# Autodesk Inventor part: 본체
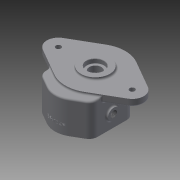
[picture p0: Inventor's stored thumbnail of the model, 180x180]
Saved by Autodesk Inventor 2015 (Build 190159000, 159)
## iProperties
Created: 2025-11
Part Number: 본체
Material: 일반
Document SubType Name: Modeling
Designer: user
Density: 1 g/cm^3
Appearance: 기본값
Author: user
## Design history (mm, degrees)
sketch "스케치1"
  geometry: L1 (-74, 17.321)-(-26, 45.033); L2 (-74, -17.321)-(-26, -45.033); L3 (26, 45.033)-(74, 17.321); L4 (74, -17.321)-(26, -45.033); A1 r 52 centre (0, 0) between (-26, 45.033) and (-26, -45.033); A2 r 20 centre (-64, 0) between (-74, 17.321) and (-74, -17.321); A3 r 20 centre (64, 0) between (74, -17.321) and (74, 17.321); 1 further point
  constraints: 8 end point, 8 point on circle, 8 tangent, 3 centre point, 2 horizontal alignment, 1 coincident
  dimensions: "d0" = 104 diameter of A1; "d1" = 40 diameter of A2; "d2" = 40 diameter of A3; "d3" = 128 distance of A3.centre A2.centre; "d4" = 64 distance of A3.centre point (0, 0)
extrude "돌출1" new body sketch "스케치1" distance "d5" = 12; taper "d6" = 0 deg
sketch "스케치2"
  geometry: C1 r 10 at (64, 0); C2 r 10 at (-64, 0); A1 r 20 centre (64, 0) between (74, -17.321) and (74, 17.321) reference; A2 r 20 centre (-64, 0) between (-74, 17.321) and (-74, -17.321) reference
  constraints: 2 centre point, 2 coincident
  dimensions: "d7" = 20 diameter of C1; "d8" = 20 diameter of C2
extrude "돌출2" join sketch "스케치2" distance "d9" = 3; taper "d10" = 0 deg
sketch "스케치3"
  geometry: A1 r 20 centre (-64, 0) between (-74, 17.321) and (-74, -17.321) reference; A2 r 20 centre (64, 0) between (74, -17.321) and (74, 17.321) reference
hole "구멍1" sketch "스케치3" at (-64, 0), (64, 0) diameter "d11" = 9; stored, may be unused: countersink angle "d15" = 90 deg, drill point angle "d17" = 118 deg; dims "d12" = 6.35, "d13" = 4, "d14" = 2, "d16" = 9.525
sketch "스케치4"
  geometry: L1 (19, -64.909)-(37.5, -54.228); L2 (45, -41.238)-(45, 9.238); L3 (37.5, 22.228)-(19, 32.909); L4 (0, -75.879)-(0, 43.879); L5 (-45, -41.238)-(-45, 9.238); L6 (-19, -64.909)-(-37.5, -54.228); L7 (-37.5, 22.228)-(-19, 32.909); L8 (-45, -16)-(45, -16); A1 r 52 centre (0, 0) between (26, 45.033) and (-26, 45.033) reference; A2 r 52 centre (0, 0) between (-26, -45.033) and (26, -45.033) reference; A3 r 38 centre (0, -32) between (-19, -64.909) and (19, -64.909); A4 r 38 centre (0, 0) between (19, 32.909) and (-19, 32.909); A5 r 15 centre (-30, -41.238) between (-45, -41.238) and (-37.5, -54.228); A6 r 15 centre (30, -41.238) between (37.5, -54.228) and (45, -41.238); A7 r 15 centre (30, 9.238) between (45, 9.238) and (37.5, 22.228); A8 r 15 centre (-30, 9.238) between (-37.5, 22.228) and (-45, 9.238); 6 further points
  constraints: 16 end point, 14 point on circle, 13 point on line, 12 tangent, 6 centre point, 4 equal radius, 2 horizontal alignment, 2 midpoint, 2 symmetric about line, 2 vertical, 2 vertical alignment, 1 coincident
  dimensions: "d19" = 90 distance between parallel lines of L5 L2; "d20" = 60 deg angle of L3 L1; "d23" = 16 distance from line of L8 A1.centre; "d25" = 38 radius of A3; "d26" = 15 radius of A5; "d33" = 32 distance of A3.centre A1.centre
node "작업 평면1"
extrude "돌출4" join sketch "스케치4" distance "d34" = 48; taper "d36" = 0 deg; dims "d35" = 8, "d37" = 0
sketch "스케치5"
  geometry: C1 r 25 at (0, 0); A1 r 52 centre (0, 0) between (26, 45.033) and (-26, 45.033) reference
  constraints: 1 centre point, 1 coincident
  dimensions: "d38" = 50 diameter of C1
extrude "돌출5" join sketch "스케치5" distance "d39" = 4; taper "d40" = 0 deg
sketch "스케치8"
  geometry: L1 (45, -41.238)-(45, 9.238) reference; L2 (16, -23.754)-(16, -8.246); L3 (-16, -23.754)-(-16, -8.246); A1 r 38 centre (0, -32) between (-19, -64.909) and (19, -64.909) reference; A2 r 38 centre (0, 0) between (19, 32.909) and (-19, 32.909) reference; A3 r 18 centre (0, -32) between (16, -23.754) and (-16, -23.754); A4 r 18 centre (0, 0) between (16, -8.246) and (-16, -8.246)
  constraints: 4 end point, 4 point on circle, 2 centre point, 2 coincident, 2 parallel
  dimensions: "d41" = 36 diameter of A3; "d42" = 36 diameter of A4; "d43" = 32 distance between parallel lines of L2 L3; "d44" = 16 distance from line of A3.centre L2
extrude "돌출6" cut sketch "스케치8" distance "d45" = 31; taper "d46" = 0 deg
sketch "스케치9"
  geometry: C1 r 25 at (0, 0) reference
hole "구멍2" sketch "스케치9" at (0, 0) diameter "d47" = 21; stored, may be unused: countersink angle "d51" = 90 deg, drill point angle "d53" = 118 deg; dims "d48" = 6.35, "d49" = 30, "d50" = 7.3, "d52" = 9.525
sketch "스케치10"
  geometry: L1 (-16, -8.246)-(-16, -23.754) reference; L2 (16, -23.754)-(16, -8.246) reference; L3 (-37.5, 22.228)-(-19, 32.909) reference; L4 (19, 32.909)-(37.5, 22.228) reference; L5 (45, 9.238)-(45, -41.238) reference; L6 (37.5, -54.228)-(19, -64.909) reference; L7 (-19, -64.909)-(-37.5, -54.228) reference; L8 (-45, -41.238)-(-45, 9.238) reference; C1 r 10.5 at (0, 0) reference; C2 r 10.5 at (0, 0) reference; C3 r 11.5 at (0, 0); A1 r 18 centre (0, -32) between (-16, -23.754) and (16, -23.754) reference; A2 r 18 centre (0, 0) between (16, -8.246) and (-16, -8.246) reference; A3 r 38 centre (0, 0) between (19, 32.909) and (-19, 32.909) reference; A4 r 15 centre (30, 9.238) between (45, 9.238) and (37.5, 22.228) reference; A5 r 15 centre (30, -41.238) between (37.5, -54.228) and (45, -41.238) reference; A6 r 38 centre (0, -32) between (-19, -64.909) and (19, -64.909) reference; A7 r 15 centre (-30, -41.238) between (-45, -41.238) and (-37.5, -54.228) reference; A8 r 15 centre (-30, 9.238) between (-37.5, 22.228) and (-45, 9.238) reference
  constraints: 1 centre point, 1 coincident
  dimensions: "d54" = 23 diameter of C3
extrude "돌출7" cut sketch "스케치10" distance "d55" = 15; taper "d56" = 0 deg
sketch "스케치11"
  geometry: C1 r 11.5 at (0, -32); A1 r 18 centre (0, -32) between (-16, -23.754) and (16, -23.754) reference
  constraints: 1 centre point, 1 coincident
  dimensions: "d57" = 23 diameter of C1
extrude "돌출8" cut sketch "스케치11" distance "d58" = 15; taper "d59" = 0 deg
sketch "스케치12"
  geometry: L1 (48, 43.301)-(48, -7.174) reference; L2 (-8, -7.174)-(-8, 0) reference; L3 (0, 0)-(-8, 0) reference; L4 (0, 43.301)-(0, 0) reference; L5 (0, 68.127)-(0, 43.301) reference; L6 (-12, 68.127)-(0, 68.127) reference; L7 (-12, 0)-(-12, 68.127) reference; L8 (-8, 0)-(-12, 0) reference; L9 (-8, -7.174)-(48, -7.174) reference; L10 (48, 43.301)-(48, -7.174) reference; L11 (0, 43.301)-(48, 43.301) reference; L12 (-16, 59.064)-(-16, 9.064) reference; C1 r 10 at (25, 18.064); 1 further point
  constraints: 1 centre point
  dimensions: "d60" = 20 diameter of C1; "d62" = 23 distance from line of L1 C1.centre; "d109" = 16 vertical distance of point (0, 34.064) C1.centre
extrude "돌출9" join sketch "스케치12" distance "d63" = 3; taper "d64" = 0 deg
sketch "스케치13"
  geometry: C1 r 10 at (0, 0) reference; 1 further point
hole "구멍3" sketch "스케치13" at (0, 0) diameter "d65" = 10.5; stored, may be unused: countersink angle "d71" = 90 deg, drill point angle "d73" = 118 deg; dims "d66" = 11, "d67" = 0.62479, "d68" = 10.589, "d69" = 30, "d70" = 7.3, "d72" = 17.5
sketch "스케치14"
  geometry: C1 r 10 at (0, 0) reference; 1 further point
hole "구멍4" sketch "스케치14" at (0, 0) diameter "d74" = 10.5; stored, may be unused: countersink angle "d80" = 90 deg, drill point angle "d82" = 118 deg; dims "d75" = 11, "d76" = 0.62479, "d77" = 10.589, "d78" = 30, "d79" = 7.3, "d81" = 17.5
sketch "스케치15"
  geometry: L1 (-45, 9.238)-(-45, -41.238) reference; L2 (45, -41.238)-(45, 9.238) reference; L3 (45, -16)-(-45, -16); A1 r 18 centre (0, -32) between (-16, -23.754) and (16, -23.754) reference; 4 further points
  constraints: 2 end point, 2 horizontal alignment, 2 midpoint, 2 vertical alignment
  dimensions: "d83" = 54 distance of point (-34, 11) point (-34, -43); "d84" = 68 distance of point (-34, -43) point (34, -43); "d85" = 34 horizontal distance of point (34, -43) A1.centre; "d86" = 27 distance from line of L3 point (-34, -43)
hole "구멍5" sketch "스케치15" at (34, -43), (-34, -43), (-34, 11), (34, 11) diameter "d87" = 4.917; stored, may be unused: countersink angle "d91" = 90 deg, drill point angle "d93" = 118 deg; dims "d88" = 12, "d89" = 30, "d90" = 7.3, "d92" = 14
node "작업 평면3"
sketch "스케치16"
  geometry: L1 (-19, -48)-(19, -48) reference; 2 further points
  constraints: 1 vertical alignment, 1 other
  dimensions: "d94" = 16 distance from line of L1 point (0, -32)
feature "엠보싱1" sketch "스케치16" dims "d1" = 40, "d95" = 0.5, "d96" = 0
fillet "모깎기1" dims "d97" = 0.3
chamfer "모따기1" distance "d98" = 0.7; stored, may be unused: second distance "d99" = 2, angle "d100" = 30 deg
fillet "모깎기2" dims "d101" = 3
fillet "모깎기3" dims "d102" = 3
fillet "모깎기4" dims "d103" = 3
chamfer "모따기2" distance "d104" = 1; stored, may be unused: second distance "d105" = 2, angle "d106" = 30 deg
fillet "모깎기5" dims "d107" = 3
fillet "모깎기6" dims "d108" = 3
chamfer "모따기3" distance "d110" = 1; stored, may be unused: second distance "d111" = 2, angle "d112" = 45 deg
fillet "모깎기7" dims "d113" = 3
node "솔리드1"
mirror "대칭1"
node "절단 모서리 투영2"
node "절단 모서리 투영3"
other parameters: "d27" = -64
